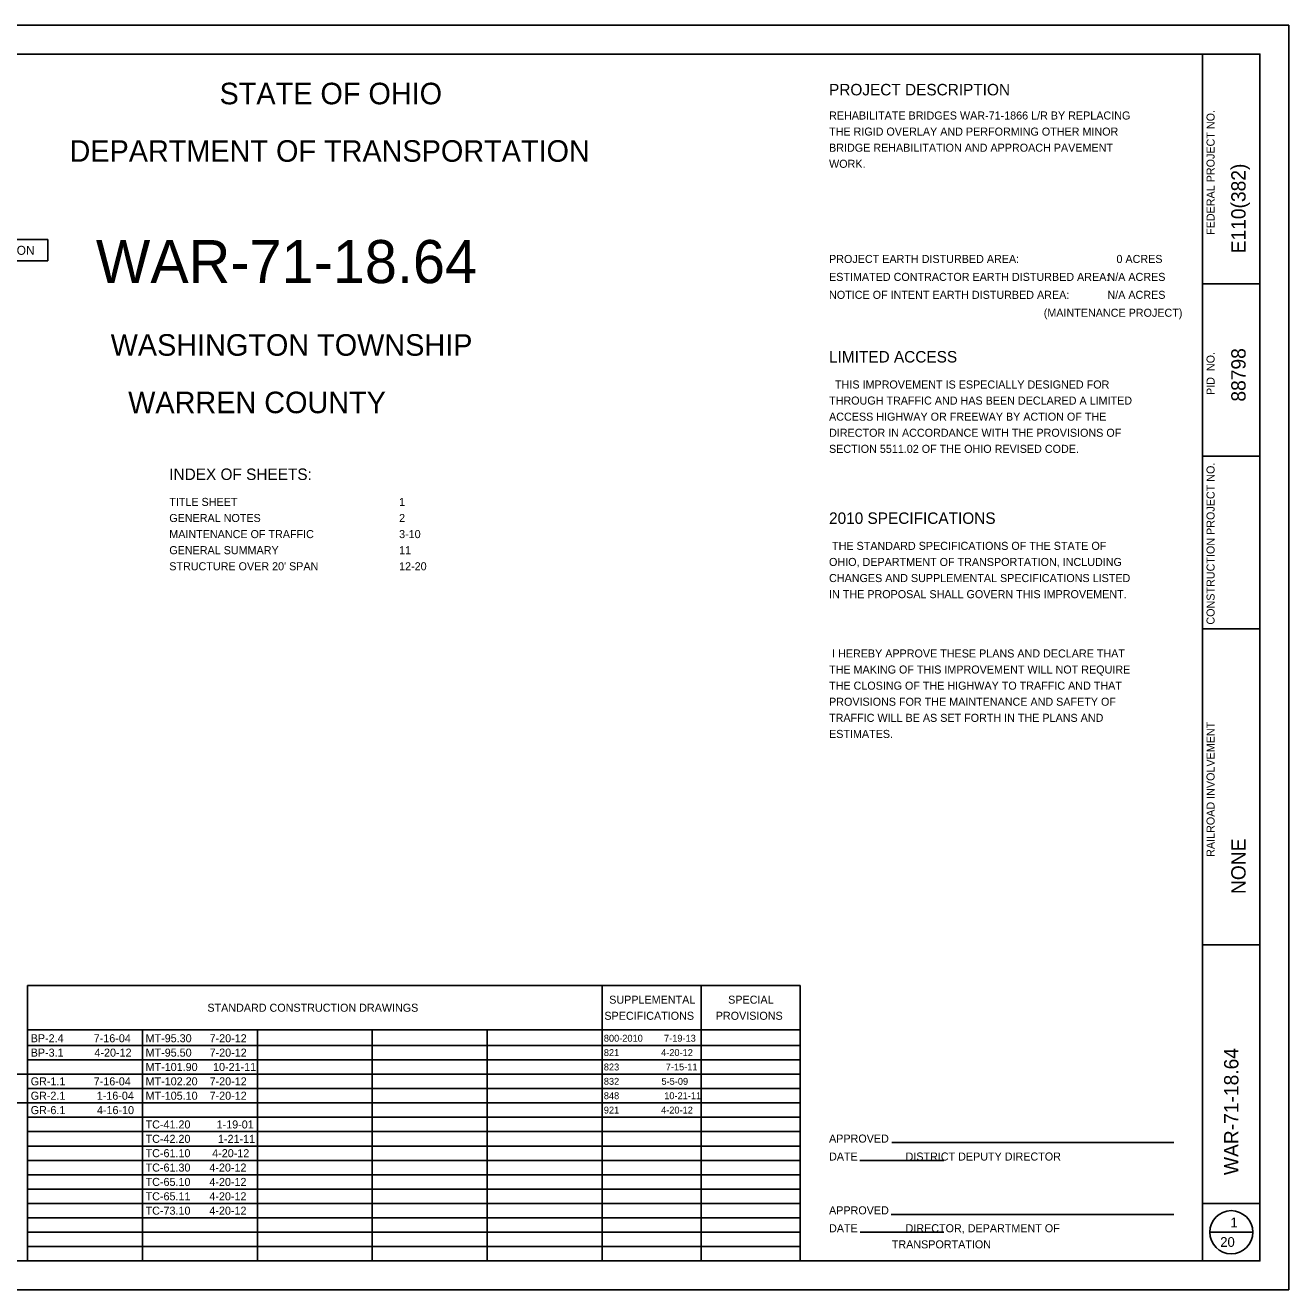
# Model space of a CAD drawing. Extents: x 0.4 to 34.4, y -2.1 to 19.9.
# Drawn here: x 12.41 to 34.4, y -2.06 to 19.94 of the extents above; entities that cross this region are included whole.
import ezdxf

# ---------------------------------------------------------------- set-up
doc = ezdxf.new("R2010")
doc.units = 0
for name, color, linetype in [('SH_Border', 7, 'Continuous'), ('SH_Cut_Line', 7, 'Continuous'), ('SH_Data', 7, 'Continuous')]:
    doc.layers.add(name, color=color, linetype=linetype)

msp = doc.modelspace()

# ---------------------------------------------------------------- linework, layer by layer
at = {"layer": 'SH_Border'}
for p, q in [((32.9, -1.564), (32.9, 19.436)), ((32.9, 15.436), (33.9, 15.436)), ((32.9, 12.436), (33.9, 12.436)), ((32.9, 9.436), (33.9, 9.436)), ((32.9, 3.936), (33.9, 3.936)), ((32.9, -0.564), (33.9, -0.564))]:
    msp.add_line(p, q, dxfattribs=at)
msp.add_lwpolyline([(2.4, 19.436), (33.9, 19.436), (33.9, -1.564), (2.4, -1.564)], close=True, dxfattribs=at)
at = {"layer": 'SH_Cut_Line'}
msp.add_lwpolyline([(0.4, -2.064), (34.4, -2.064), (34.4, 19.936), (0.4, 19.936)], close=True, dxfattribs=at)
at = {"layer": 'SH_Data'}
for p, q in [((12.45, 3.227), (25.9, 3.227)), ((12.45, -1.564), (12.45, 3.227)), ((22.45, -1.564), (22.45, 3.227)), ((24.175, -1.564), (24.175, 3.227)), ((25.9, -1.564), (25.9, 3.227)), ((12.45, 2.457), (25.9, 2.457)), ((14.45, -1.564), (14.45, 2.457)), ((16.45, -1.564), (16.45, 2.457)), ((18.45, -1.564), (18.45, 2.457)), ((20.45, -1.564), (20.45, 2.457)), ((12.45, 2.186), (25.9, 2.186)), ((12.45, 1.936), (25.9, 1.936)), ((9.65, 1.686), (12.45, 1.686)), ((12.45, 1.686), (25.9, 1.686)), ((12.45, 1.436), (25.9, 1.436)), ((9.65, 1.186), (12.45, 1.186)), ((12.45, 1.186), (25.9, 1.186)), ((12.45, 0.936), (25.9, 0.936)), ((12.45, 0.686), (25.9, 0.686)), ((27.495, 0.495), (32.4, 0.495)), ((12.45, 0.436), (25.9, 0.436)), ((12.45, 0.186), (25.9, 0.186)), ((26.933, 0.183), (28.4, 0.183)), ((12.45, -0.064), (25.9, -0.064)), ((12.45, -0.314), (25.9, -0.314)), ((12.45, -0.564), (25.9, -0.564)), ((12.45, -0.814), (25.9, -0.814)), ((27.48, -0.753), (32.4, -0.753)), ((12.45, -1.064), (25.9, -1.064)), ((26.942, -1.065), (28.4, -1.065)), ((33.025, -1.064), (33.775, -1.064)), ((12.45, -1.314), (25.9, -1.314))]:
    msp.add_line(p, q, dxfattribs=at)
msp.add_lwpolyline([(12.801, 16.207), (10.405, 16.207), (10.405, 15.838), (12.801, 15.838)], close=True, dxfattribs=at)
msp.add_circle((33.4, -1.064), 0.375, dxfattribs=at)

# ---------------------------------------------------------------- texts
for s, height, p in [('STATE OF OHIO', 0.375, (15.792, 18.561)), ('PROJECT DESCRIPTION', 0.2, (26.4, 18.716)), ('REHABILITATE BRIDGES WAR-71-1866 L/R BY REPLACING ', 0.14, (26.4, 18.296)), ('THE RIGID OVERLAY AND PERFORMING OTHER MINOR   ', 0.14, (26.4, 18.016)), ('DEPARTMENT OF TRANSPORTATION', 0.375, (13.181, 17.561)), ('BRIDGE REHABILITATION AND APPROACH PAVEMENT   ', 0.14, (26.4, 17.736)), ('WORK.                                              ', 0.14, (26.4, 17.456)), ('PROJECT LOCATION', 0.156, (10.476, 15.942)), ('WAR-71-18.64', 0.75, (13.64, 15.449)), ('PROJECT EARTH DISTURBED AREA:', 0.14, (26.4, 15.8)), ('   0 ACRES', 0.14, (31.246, 15.8)), ('ESTIMATED CONTRACTOR EARTH DISTURBED AREA:', 0.14, (26.4, 15.488)), (' N/A ACRES', 0.14, (31.193, 15.488)), ('NOTICE OF INTENT EARTH DISTURBED AREA:', 0.14, (26.4, 15.176)), (' N/A ACRES', 0.14, (31.193, 15.176)), ('(MAINTENANCE PROJECT)', 0.14, (30.137, 14.864)), ('WASHINGTON TOWNSHIP', 0.375, (13.897, 14.186)), ('LIMITED ACCESS', 0.2, (26.4, 14.068)), ('  THIS IMPROVEMENT IS ESPECIALLY DESIGNED FOR', 0.14, (26.4, 13.616)), ('   WARREN COUNTY   ', 0.375, (13.784, 13.186)), ('THROUGH TRAFFIC AND HAS BEEN DECLARED A LIMITED', 0.14, (26.4, 13.336)), ('ACCESS HIGHWAY OR FREEWAY BY ACTION OF THE', 0.14, (26.4, 13.056)), ('DIRECTOR IN ACCORDANCE WITH THE PROVISIONS OF', 0.14, (26.4, 12.776)), ('SECTION 5511.02 OF THE OHIO REVISED CODE.', 0.14, (26.4, 12.496)), ('INDEX OF SHEETS:', 0.2, (14.917, 12.024)), ('TITLE SHEET                    ', 0.14, (14.917, 11.573)), ('1      ', 0.14, (18.917, 11.573)), ('2010 SPECIFICATIONS', 0.2, (26.4, 11.26)), ('GENERAL NOTES                  ', 0.14, (14.917, 11.293)), ('2      ', 0.14, (18.917, 11.293)), ('MAINTENANCE OF TRAFFIC       ', 0.14, (14.917, 11.013)), ('3-10   ', 0.14, (18.917, 11.013)), ('GENERAL SUMMARY                ', 0.14, (14.917, 10.733)), ('11     ', 0.14, (18.917, 10.733)), (' THE STANDARD SPECIFICATIONS OF THE STATE OF', 0.14, (26.4, 10.808)), ("STRUCTURE OVER 20' SPAN      ", 0.14, (14.917, 10.453)), ('12-20  ', 0.14, (18.917, 10.453)), ('OHIO, DEPARTMENT OF TRANSPORTATION, INCLUDING', 0.14, (26.4, 10.528)), ('CHANGES AND SUPPLEMENTAL SPECIFICATIONS LISTED', 0.14, (26.4, 10.248)), ('IN THE PROPOSAL SHALL GOVERN THIS IMPROVEMENT.', 0.14, (26.4, 9.968)), (' I HEREBY APPROVE THESE PLANS AND DECLARE THAT', 0.14, (26.4, 8.936)), ('THE MAKING OF THIS IMPROVEMENT WILL NOT REQUIRE', 0.14, (26.4, 8.656)), ('THE CLOSING OF THE HIGHWAY TO TRAFFIC AND THAT', 0.14, (26.4, 8.376)), ('PROVISIONS FOR THE MAINTENANCE AND SAFETY OF', 0.14, (26.4, 8.096)), ('TRAFFIC WILL BE AS SET FORTH IN THE PLANS AND', 0.14, (26.4, 7.816)), ('ESTIMATES.', 0.14, (26.4, 7.536)), ('STANDARD CONSTRUCTION DRAWINGS', 0.14, (15.58, 2.772)), ('SUPPLEMENTAL', 0.14, (22.574, 2.912)), ('SPECIAL', 0.14, (24.644, 2.912)), ('SPECIFICATIONS', 0.14, (22.49, 2.632)), ('PROVISIONS', 0.14, (24.428, 2.632)), ('BP-2.4   ', 0.14, (12.505, 2.241)), (' 7-16-04', 0.14, (13.55, 2.241)), ('MT-95.30 ', 0.14, (14.505, 2.241)), (' 7-20-12', 0.14, (15.567, 2.241)), ('800-2010', 0.12, (22.48, 2.251)), (' 7-19-13', 0.12, (23.483, 2.251)), ('BP-3.1   ', 0.14, (12.505, 1.991)), (' 4-20-12', 0.14, (13.563, 1.991)), ('MT-95.50 ', 0.14, (14.505, 1.991)), (' 7-20-12', 0.14, (15.567, 1.991)), ('821', 0.12, (22.48, 2.001)), (' 4-20-12', 0.12, (23.432, 2.001)), ('MT-101.90', 0.14, (14.505, 1.741)), ('10-21-11', 0.14, (15.679, 1.741)), ('823     ', 0.12, (22.48, 1.751)), (' 7-15-11', 0.12, (23.513, 1.751)), ('GR-1.1   ', 0.14, (12.505, 1.491)), (' 7-16-04', 0.14, (13.55, 1.491)), ('MT-102.20', 0.14, (14.505, 1.491)), (' 7-20-12', 0.14, (15.567, 1.491)), ('832     ', 0.12, (22.48, 1.501)), ('  5-5-09', 0.12, (23.394, 1.501)), ('GR-2.1   ', 0.14, (12.505, 1.241)), (' 1-16-04', 0.14, (13.603, 1.241)), ('MT-105.10', 0.14, (14.505, 1.241)), (' 7-20-12', 0.14, (15.567, 1.241)), ('848     ', 0.12, (22.48, 1.251)), ('10-21-11', 0.12, (23.531, 1.251)), ('GR-6.1   ', 0.14, (12.505, 0.991)), (' 4-16-10', 0.14, (13.606, 0.991)), ('921     ', 0.12, (22.48, 1.001)), (' 4-20-12', 0.12, (23.432, 1.001)), ('TC-41.20 ', 0.14, (14.505, 0.741)), ('1-19-01', 0.14, (15.741, 0.741)), ('TC-42.20 ', 0.14, (14.505, 0.491)), (' 1-21-11', 0.14, (15.713, 0.491)), ('APPROVED', 0.14, (26.4, 0.495)), ('TC-61.10 ', 0.14, (14.505, 0.241)), ('4-20-12', 0.14, (15.664, 0.241)), ('DATE                DISTRICT DEPUTY DIRECTOR', 0.14, (26.4, 0.183)), ('TC-61.30 ', 0.14, (14.505, -0.009)), (' 4-20-12', 0.14, (15.563, -0.009)), ('TC-65.10 ', 0.14, (14.505, -0.259)), (' 4-20-12', 0.14, (15.563, -0.259)), ('TC-65.11 ', 0.14, (14.505, -0.509)), (' 4-20-12', 0.14, (15.563, -0.509)), ('TC-73.10 ', 0.14, (14.505, -0.759)), (' 4-20-12', 0.14, (15.563, -0.759)), ('APPROVED', 0.14, (26.4, -0.753)), ('1', 0.17, (33.386, -0.979)), ('DATE                DIRECTOR, DEPARTMENT OF', 0.14, (26.4, -1.065)), ('                     TRANSPORTATION', 0.14, (26.4, -1.345)), (' 20 ', 0.17, (33.145, -1.319))]:
    msp.add_text(s, height=height, dxfattribs=at).set_placement(p)
for s, height, p in [('FEDERAL PROJECT NO.', 0.14, (33.11, 16.288)), ('   E110(382)    ', 0.25, (33.65, 15.689)), ('88798', 0.25, (33.65, 13.388)), ('PID  NO.', 0.14, (33.11, 13.503)), ('CONSTRUCTION PROJECT NO.', 0.14, (33.11, 9.508)), ('RAILROAD INVOLVEMENT', 0.14, (33.11, 5.467)), ('       NONE        ', 0.25, (33.65, 4.17)), ('  WAR-71-18.64  ', 0.25, (33.525, -0.256))]:
    msp.add_text(s, height=height, rotation=90, dxfattribs=at).set_placement(p)

doc.saveas('drawing.dxf')
